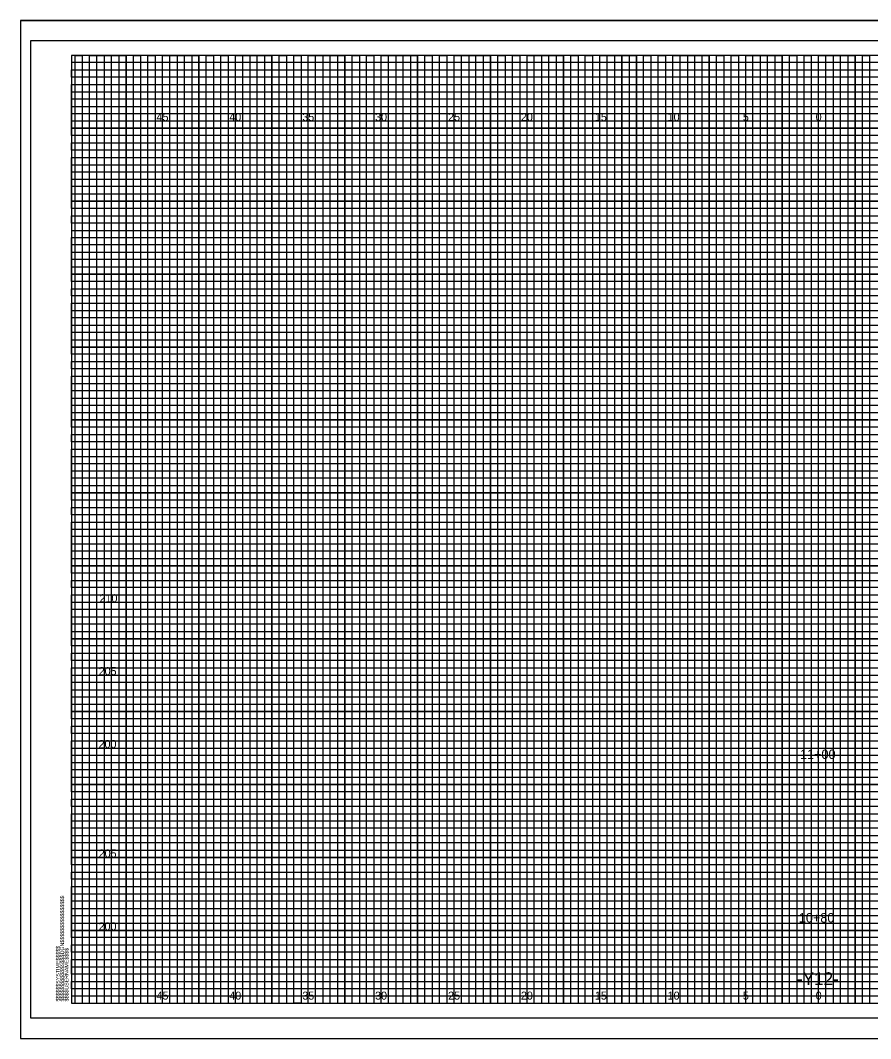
# Model space of a CAD drawing. Extents: x -4 to 103, y -2 to 138.
# Drawn here: x -3.5 to 54.8, y 68.4 to 138.2 of the extents above; entities that cross this region are included whole.
import ezdxf

# ---------------------------------------------------------------- set-up
doc = ezdxf.new("R2010")
doc.units = 0
for name, color, linetype in [('Exist XS Ground Line', 7, 'Continuous'), ('Old_Level_10', 7, 'Continuous'), ('Old_Level_16', 7, 'Continuous'), ('Old_Level_3', 7, 'Continuous'), ('Old_Level_5', 7, 'Continuous'), ('Old_Level_8', 7, 'Continuous'), ('Prop XS Dump Level', 7, 'Continuous'), ('Prop XS Elevation Labels', 7, 'Continuous'), ('Prop XS EOT Tick Mark', 7, 'Continuous'), ('Prop XS Finish Grade', 7, 'Continuous'), ('Prop XS Suitable Common Exc Shape', 7, 'Continuous')]:
    doc.layers.add(name, color=color, linetype=linetype)

msp = doc.modelspace()

# ---------------------------------------------------------------- linework, layer by layer
at = {"layer": 'Exist XS Ground Line'}
msp.add_lwpolyline([(103, 136.825), (-2.8, 136.825), (-2.8, 69.825), (103, 69.825)], close=True, dxfattribs=at)
at = {"layer": 'Old_Level_10'}
for p, q in [((1.25, 70.825), (1.25, 135.825)), ((3.75, 70.825), (3.75, 135.825)), ((6.25, 70.825), (6.25, 135.825)), ((8.75, 70.825), (8.75, 135.825)), ((11.25, 70.825), (11.25, 135.825)), ((13.75, 70.825), (13.75, 135.825)), ((16.25, 70.825), (16.25, 135.825)), ((18.75, 70.825), (18.75, 135.825)), ((21.25, 70.825), (21.25, 135.825)), ((23.75, 70.825), (23.75, 135.825)), ((26.25, 70.825), (26.25, 135.825)), ((28.75, 70.825), (28.75, 135.825)), ((31.25, 70.825), (31.25, 135.825)), ((33.75, 70.825), (33.75, 135.825)), ((36.25, 70.825), (36.25, 135.825)), ((38.75, 70.825), (38.75, 135.825)), ((41.25, 70.825), (41.25, 135.825)), ((43.75, 70.825), (43.75, 135.825)), ((46.25, 70.825), (46.25, 135.825)), ((48.75, 70.825), (48.75, 135.825)), ((51.25, 70.825), (51.25, 135.825)), ((53.75, 70.825), (53.75, 135.825)), ((0, 133.325), (74.25, 133.325)), ((0, 130.825), (102.5, 130.825)), ((0, 128.325), (102.5, 128.325)), ((0, 125.825), (102.5, 125.825)), ((0, 123.325), (102.5, 123.325)), ((0, 120.825), (102.5, 120.825)), ((0, 118.325), (102.5, 118.325)), ((0, 115.825), (102.5, 115.825)), ((0, 113.325), (102.5, 113.325)), ((0, 110.825), (102.5, 110.825)), ((0, 108.325), (102.5, 108.325)), ((0, 105.825), (102.5, 105.825)), ((0, 103.325), (102.5, 103.325)), ((0, 100.825), (102.5, 100.825)), ((0, 98.325), (102.5, 98.325)), ((0, 95.825), (102.5, 95.825)), ((0, 93.325), (102.5, 93.325)), ((0, 90.825), (102.5, 90.825)), ((0, 88.325), (102.5, 88.325)), ((0, 85.825), (102.5, 85.825)), ((0, 83.325), (102.5, 83.325)), ((0, 80.825), (102.5, 80.825)), ((0, 78.325), (102.5, 78.325)), ((0, 75.825), (102.5, 75.825)), ((0, 73.325), (102.5, 73.325))]:
    msp.add_line(p, q, dxfattribs=at)
at = {"layer": 'Old_Level_3'}
for p, q in [((-3.5, 138.225), (103.4, 138.225)), ((-3.5, 138.225), (-3.5, 68.4)), ((-3.5, 68.4), (103.4, 68.4))]:
    msp.add_line(p, q, dxfattribs=at)
at = {"layer": 'Old_Level_5'}
msp.add_lwpolyline([(103.4, 138.225), (-3.5, 138.225), (-3.5, 68.4), (103.4, 68.4)], close=True, dxfattribs=at)
at = {"layer": 'Old_Level_8'}
for points in [[(1.25, 70.825), (1.25, 135.825), (3.75, 135.825), (3.75, 70.825), (6.25, 70.825), (6.25, 135.825), (8.75, 135.825), (8.75, 70.825), (11.25, 70.825), (11.25, 135.825), (13.75, 135.825), (13.75, 70.825), (16.25, 70.825), (16.25, 135.825), (18.75, 135.825), (18.75, 70.825), (21.25, 70.825), (21.25, 135.825), (23.75, 135.825), (23.75, 70.825), (26.25, 70.825), (26.25, 135.825), (28.75, 135.825), (28.75, 70.825), (31.25, 70.825), (31.25, 135.825), (33.75, 135.825), (33.75, 70.825), (36.25, 70.825), (36.25, 135.825), (38.75, 135.825), (38.75, 70.825), (41.25, 70.825), (41.25, 135.825), (43.75, 135.825), (43.75, 70.825), (46.25, 70.825), (46.25, 135.825), (48.75, 135.825), (48.75, 70.825), (51.25, 70.825), (51.25, 135.825), (53.75, 135.825), (53.75, 70.825)], [(102.5, 130.825), (0, 130.825), (0, 133.325), (74.25, 133.325)], [(102.5, 125.825), (0, 125.825), (0, 128.325), (102.5, 128.325)], [(102.5, 120.825), (0, 120.825), (0, 123.325), (102.5, 123.325)], [(102.5, 115.825), (0, 115.825), (0, 118.325), (102.5, 118.325)], [(102.5, 110.825), (0, 110.825), (0, 113.325), (102.5, 113.325)], [(102.5, 105.825), (0, 105.825), (0, 108.325), (102.5, 108.325)], [(102.5, 100.825), (0, 100.825), (0, 103.325), (102.5, 103.325)], [(102.5, 95.825), (0, 95.825), (0, 98.325), (102.5, 98.325)], [(102.5, 90.825), (0, 90.825), (0, 93.325), (102.5, 93.325)], [(102.5, 85.825), (0, 85.825), (0, 88.325), (102.5, 88.325)], [(102.5, 80.825), (0, 80.825), (0, 83.325), (102.5, 83.325)], [(102.5, 75.825), (0, 75.825), (0, 78.325), (102.5, 78.325)], [(0, 73.325), (102.5, 73.325)]]:
    msp.add_lwpolyline(points, dxfattribs=at)
at = {"layer": 'Prop XS Elevation Labels'}
msp.add_lwpolyline([(102.5, 135.825), (0, 135.825), (0, 70.825), (102.5, 70.825)], close=True, dxfattribs=at)
at = {"layer": 'Prop XS Finish Grade'}
for points in [[(0.25, 70.825), (0.25, 135.825), (0.75, 135.825), (0.75, 70.825), (1.75, 70.825), (1.75, 135.825), (2.25, 135.825), (2.25, 70.825), (2.75, 70.825), (2.75, 135.825), (3.25, 135.825), (3.25, 70.825), (4.25, 70.825), (4.25, 135.825), (4.75, 135.825), (4.75, 70.825), (5.25, 70.825), (5.25, 135.825), (5.75, 135.825), (5.75, 70.825), (6.75, 70.825), (6.75, 135.825), (7.25, 135.825), (7.25, 70.825), (7.75, 70.825), (7.75, 135.825), (8.25, 135.825), (8.25, 70.825), (9.25, 70.825), (9.25, 135.825), (9.75, 135.825), (9.75, 70.825), (10.25, 70.825), (10.25, 135.825), (10.75, 135.825), (10.75, 70.825), (11.75, 70.825), (11.75, 135.825), (12.25, 135.825), (12.25, 70.825), (12.75, 70.825), (12.75, 135.825), (13.25, 135.825), (13.25, 70.825), (14.25, 70.825), (14.25, 135.825), (14.75, 135.825), (14.75, 70.825), (15.75, 70.825), (15.25, 70.825), (15.25, 135.825), (15.75, 135.825), (15.75, 70.825), (16.75, 70.825), (16.75, 135.825), (17.25, 135.825), (17.25, 70.825), (17.75, 70.825), (17.75, 135.825), (18.25, 135.825), (18.25, 70.825), (19.25, 70.825), (19.25, 135.825), (19.75, 135.825), (19.75, 70.825), (20.25, 70.825), (20.25, 135.825), (20.75, 135.825), (20.75, 70.825), (21.75, 70.825), (21.75, 135.825), (22.25, 135.825), (22.25, 70.825), (22.75, 70.825), (22.75, 135.825), (23.25, 135.825), (23.25, 70.825), (24.25, 70.825), (24.25, 135.825), (24.75, 135.825), (24.75, 70.825), (25.25, 70.825), (25.25, 135.825), (25.75, 135.825), (25.75, 70.825), (26.75, 70.825), (26.75, 135.825), (27.25, 135.825), (27.25, 70.825), (27.75, 70.825), (27.75, 135.825), (28.25, 135.825), (28.25, 70.825), (29.25, 70.825), (29.25, 135.825), (29.75, 135.825), (29.75, 70.825), (30.25, 70.825), (30.25, 135.825), (30.75, 135.825), (30.75, 70.825)], [(30.75, 70.825), (31.75, 70.825), (31.75, 135.825), (32.25, 135.825), (32.25, 70.825), (32.75, 70.825), (32.75, 135.825), (33.25, 135.825), (33.25, 70.825), (34.25, 70.825), (34.25, 135.825), (34.75, 135.825), (34.75, 70.825), (35.25, 70.825), (35.25, 135.825), (35.75, 135.825), (35.75, 70.825), (36.75, 70.825), (36.75, 135.825), (37.25, 135.825), (37.25, 70.825), (37.75, 70.825), (37.75, 135.825), (37.75, 70.825)], [(38.25, 135.825), (38.25, 70.825), (39.25, 70.825), (39.25, 135.825), (39.75, 135.825), (39.75, 70.825), (40.25, 70.825), (40.25, 135.825), (40.75, 135.825), (40.75, 70.825), (41.75, 70.825), (41.75, 135.825), (42.25, 135.825), (42.25, 70.825), (42.75, 70.825), (42.75, 135.825), (43.25, 135.825), (43.25, 70.825), (43.75, 70.825), (44.25, 70.825), (44.25, 135.825), (44.75, 135.825), (44.75, 70.825), (45.25, 70.825), (45.25, 135.825), (45.75, 135.825), (45.75, 70.825), (46.75, 70.825), (46.75, 135.825), (47.25, 135.825), (47.25, 70.825), (47.75, 70.825), (47.75, 135.825), (48.25, 135.825), (48.25, 70.825), (49.25, 70.825), (49.25, 135.825), (49.75, 135.825), (49.75, 70.825), (50.25, 70.825), (50.25, 135.825), (50.75, 135.825), (50.75, 70.825), (51.75, 70.825), (51.75, 135.825), (52.25, 135.825), (52.25, 70.825), (52.75, 70.825), (52.75, 135.825), (53.25, 135.825), (53.25, 70.825), (54.25, 70.825), (54.25, 135.825), (54.75, 135.825), (54.75, 70.825), (55.25, 70.825)], [(0, 132.825), (0, 133.825), (74.25, 133.825), (74.25, 134.325), (0, 134.325), (0, 134.825), (74.25, 134.825), (74.25, 135.325), (0, 135.325)], [(102.5, 132.825), (0, 132.825)], [(102.5, 131.825), (0, 131.825), (0, 132.325), (102.5, 132.325)], [(102.5, 130.325), (0, 130.325), (0, 131.325), (102.5, 131.325)], [(102.5, 129.325), (0, 129.325), (0, 129.825), (102.5, 129.825)], [(102.5, 127.825), (0, 127.825), (0, 128.825), (102.5, 128.825)], [(102.5, 126.825), (0, 126.825), (0, 127.325), (102.5, 127.325)], [(102.5, 125.325), (0, 125.325), (0, 126.325), (102.5, 126.325)], [(102.5, 124.325), (0, 124.325), (0, 124.825), (102.5, 124.825)], [(0, 123.825), (102.5, 123.825)], [(102.5, 122.825), (0, 122.825)], [(102.5, 121.825), (0, 121.825), (0, 122.325), (102.5, 122.325)], [(102.5, 120.325), (0, 120.325), (0, 121.325), (102.5, 121.325)], [(102.5, 119.325), (0, 119.325), (0, 119.825), (102.5, 119.825)], [(102.5, 117.825), (0, 117.825), (0, 118.825), (102.5, 118.825)], [(102.5, 116.825), (0, 116.825), (0, 117.325), (102.5, 117.325)], [(102.5, 115.325), (0, 115.325), (0, 116.325), (102.5, 116.325)], [(102.5, 114.325), (0, 114.325), (0, 114.825), (102.5, 114.825)], [(102.5, 112.825), (0, 112.825), (0, 113.825), (102.5, 113.825)], [(102.5, 111.825), (0, 111.825), (0, 112.325), (102.5, 112.325)], [(102.5, 110.325), (0, 110.325), (0, 111.325), (102.5, 111.325)], [(102.5, 109.325), (0, 109.325), (0, 109.825), (102.5, 109.825)], [(102.5, 107.825), (0, 107.825), (0, 108.825), (102.5, 108.825)], [(102.5, 106.825), (0, 106.825), (0, 107.325), (102.5, 107.325)], [(102.5, 105.325), (0, 105.325), (0, 106.325), (102.5, 106.325)], [(102.5, 104.325), (0, 104.325), (0, 104.825), (102.5, 104.825)], [(102.5, 102.825), (0, 102.825), (0, 103.825), (102.5, 103.825)], [(102.5, 101.825), (0, 101.825), (0, 102.325)], [(0, 102.325), (102.5, 102.325)], [(102.5, 100.325), (0, 100.325), (0, 101.325), (102.5, 101.325)], [(102.5, 99.325), (0, 99.325), (0, 99.825), (102.5, 99.825)], [(102.5, 97.825), (0, 97.825), (0, 98.825), (102.5, 98.825)], [(102.5, 96.825), (0, 96.825), (0, 97.325), (102.5, 97.325)], [(102.5, 95.325), (0, 95.325), (0, 96.325), (102.5, 96.325)], [(102.5, 94.325), (0, 94.325), (0, 94.825), (102.5, 94.825)], [(102.5, 92.825), (0, 92.825), (0, 93.825), (102.5, 93.825)], [(102.5, 91.825), (0, 91.825), (0, 92.325), (102.5, 92.325)], [(102.5, 90.325), (0, 90.325), (0, 91.325), (102.5, 91.325)], [(102.5, 89.325), (0, 89.325), (0, 89.825), (102.5, 89.825)], [(102.5, 87.825), (0, 87.825), (0, 88.825), (102.5, 88.825)], [(102.5, 86.825), (0, 86.825), (0, 87.325), (102.5, 87.325)], [(102.5, 85.325), (0, 85.325), (0, 86.325), (102.5, 86.325)], [(102.5, 84.325), (0, 84.325), (0, 84.825), (102.5, 84.825)], [(102.5, 82.825), (0, 82.825), (0, 83.825), (102.5, 83.825)], [(102.5, 81.825), (0, 81.825), (0, 82.325), (102.5, 82.325)], [(102.5, 80.325), (0, 80.325), (0, 81.325), (102.5, 81.325)], [(102.5, 79.325), (0, 79.325), (0, 79.825), (102.5, 79.825)], [(102.5, 77.825), (0, 77.825), (0, 78.825), (102.5, 78.825)], [(102.5, 76.825), (0, 76.825), (0, 77.325), (102.5, 77.325)], [(102.5, 75.325), (0, 75.325), (0, 76.325), (102.5, 76.325)], [(102.5, 74.325), (0, 74.325), (0, 74.825), (102.5, 74.825)], [(102.5, 72.825), (0, 72.825), (0, 73.825), (102.5, 73.825)], [(102.5, 71.825), (0, 71.825), (0, 72.325), (102.5, 72.325)], [(0, 71.325), (102.5, 71.325)]]:
    msp.add_lwpolyline(points, dxfattribs=at)

# ---------------------------------------------------------------- texts
at = {"layer": 'Old_Level_16'}
for s, p in [('45', (5.84, 131.325)), ('40', (10.831, 131.325)), ('35', (15.84, 131.325)), ('30', (20.831, 131.325)), ('25', (25.84, 131.325)), ('20', (30.831, 131.325)), ('15', (35.906, 131.325)), ('10', (40.897, 131.325)), ('5', (46.057, 131.325)), ('0', (51.049, 131.325)), ('0', (51.049, 131.325)), ('45', (5.84, 71.075)), ('40', (10.831, 71.075)), ('35', (15.84, 71.075)), ('30', (20.831, 71.075)), ('25', (25.84, 71.075)), ('20', (30.831, 71.075)), ('15', (35.906, 71.075)), ('10', (40.897, 71.075)), ('5', (46.057, 71.075)), ('0', (51.049, 71.075)), ('0', (51.049, 71.075))]:
    msp.add_text(s, height=0.55, dxfattribs=at).set_placement(p)
at = {"layer": 'Old_Level_8'}
msp.add_text('040397', height=0.0025, rotation=90, dxfattribs=at).set_placement((-0.001, 135.811))
at = {"layer": 'Prop XS Dump Level'}
for s, p in [('210', (1.93, 98.325)), ('205', (1.872, 93.325)), ('200', (1.864, 88.325)), ('205', (1.872, 80.825)), ('200', (1.864, 75.825))]:
    msp.add_text(s, height=0.55, dxfattribs=at).set_placement(p)
at = {"layer": 'Prop XS Elevation Labels'}
for s, p in [('$$$$$$$$$$$$$$$$DGN$$$$$$$$$$$$$$$$', (-0.5, 70.95)), ('$$$$$$SYSTIME$$$$$', (-0.797, 70.95)), ('$$$$USERNAME$$$$', (-0.2, 70.95))]:
    msp.add_text(s, height=0.2625, rotation=90, dxfattribs=at).set_placement(p)
at = {"layer": 'Prop XS EOT Tick Mark'}
msp.add_text('-Y12-', height=0.875, dxfattribs=at).set_placement((49.773, 72.075))
at = {"layer": 'Prop XS Suitable Common Exc Shape'}
for s, p in [('11+00', (49.971, 87.572)), ('10+80', (49.893, 76.362))]:
    msp.add_text(s, height=0.65, dxfattribs=at).set_placement(p)

doc.saveas('drawing.dxf')
